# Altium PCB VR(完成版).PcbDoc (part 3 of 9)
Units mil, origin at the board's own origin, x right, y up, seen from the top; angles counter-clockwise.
Board outline 2839.68 x 2020.7 mil, 6 copper layers (TOP, GND02, SIN03, SIN04, PWR05, BOTTOM); 494 components, 404 nets, 7124 pads, 1123 vias.
Unrouted connection lines stored in the file: 10.
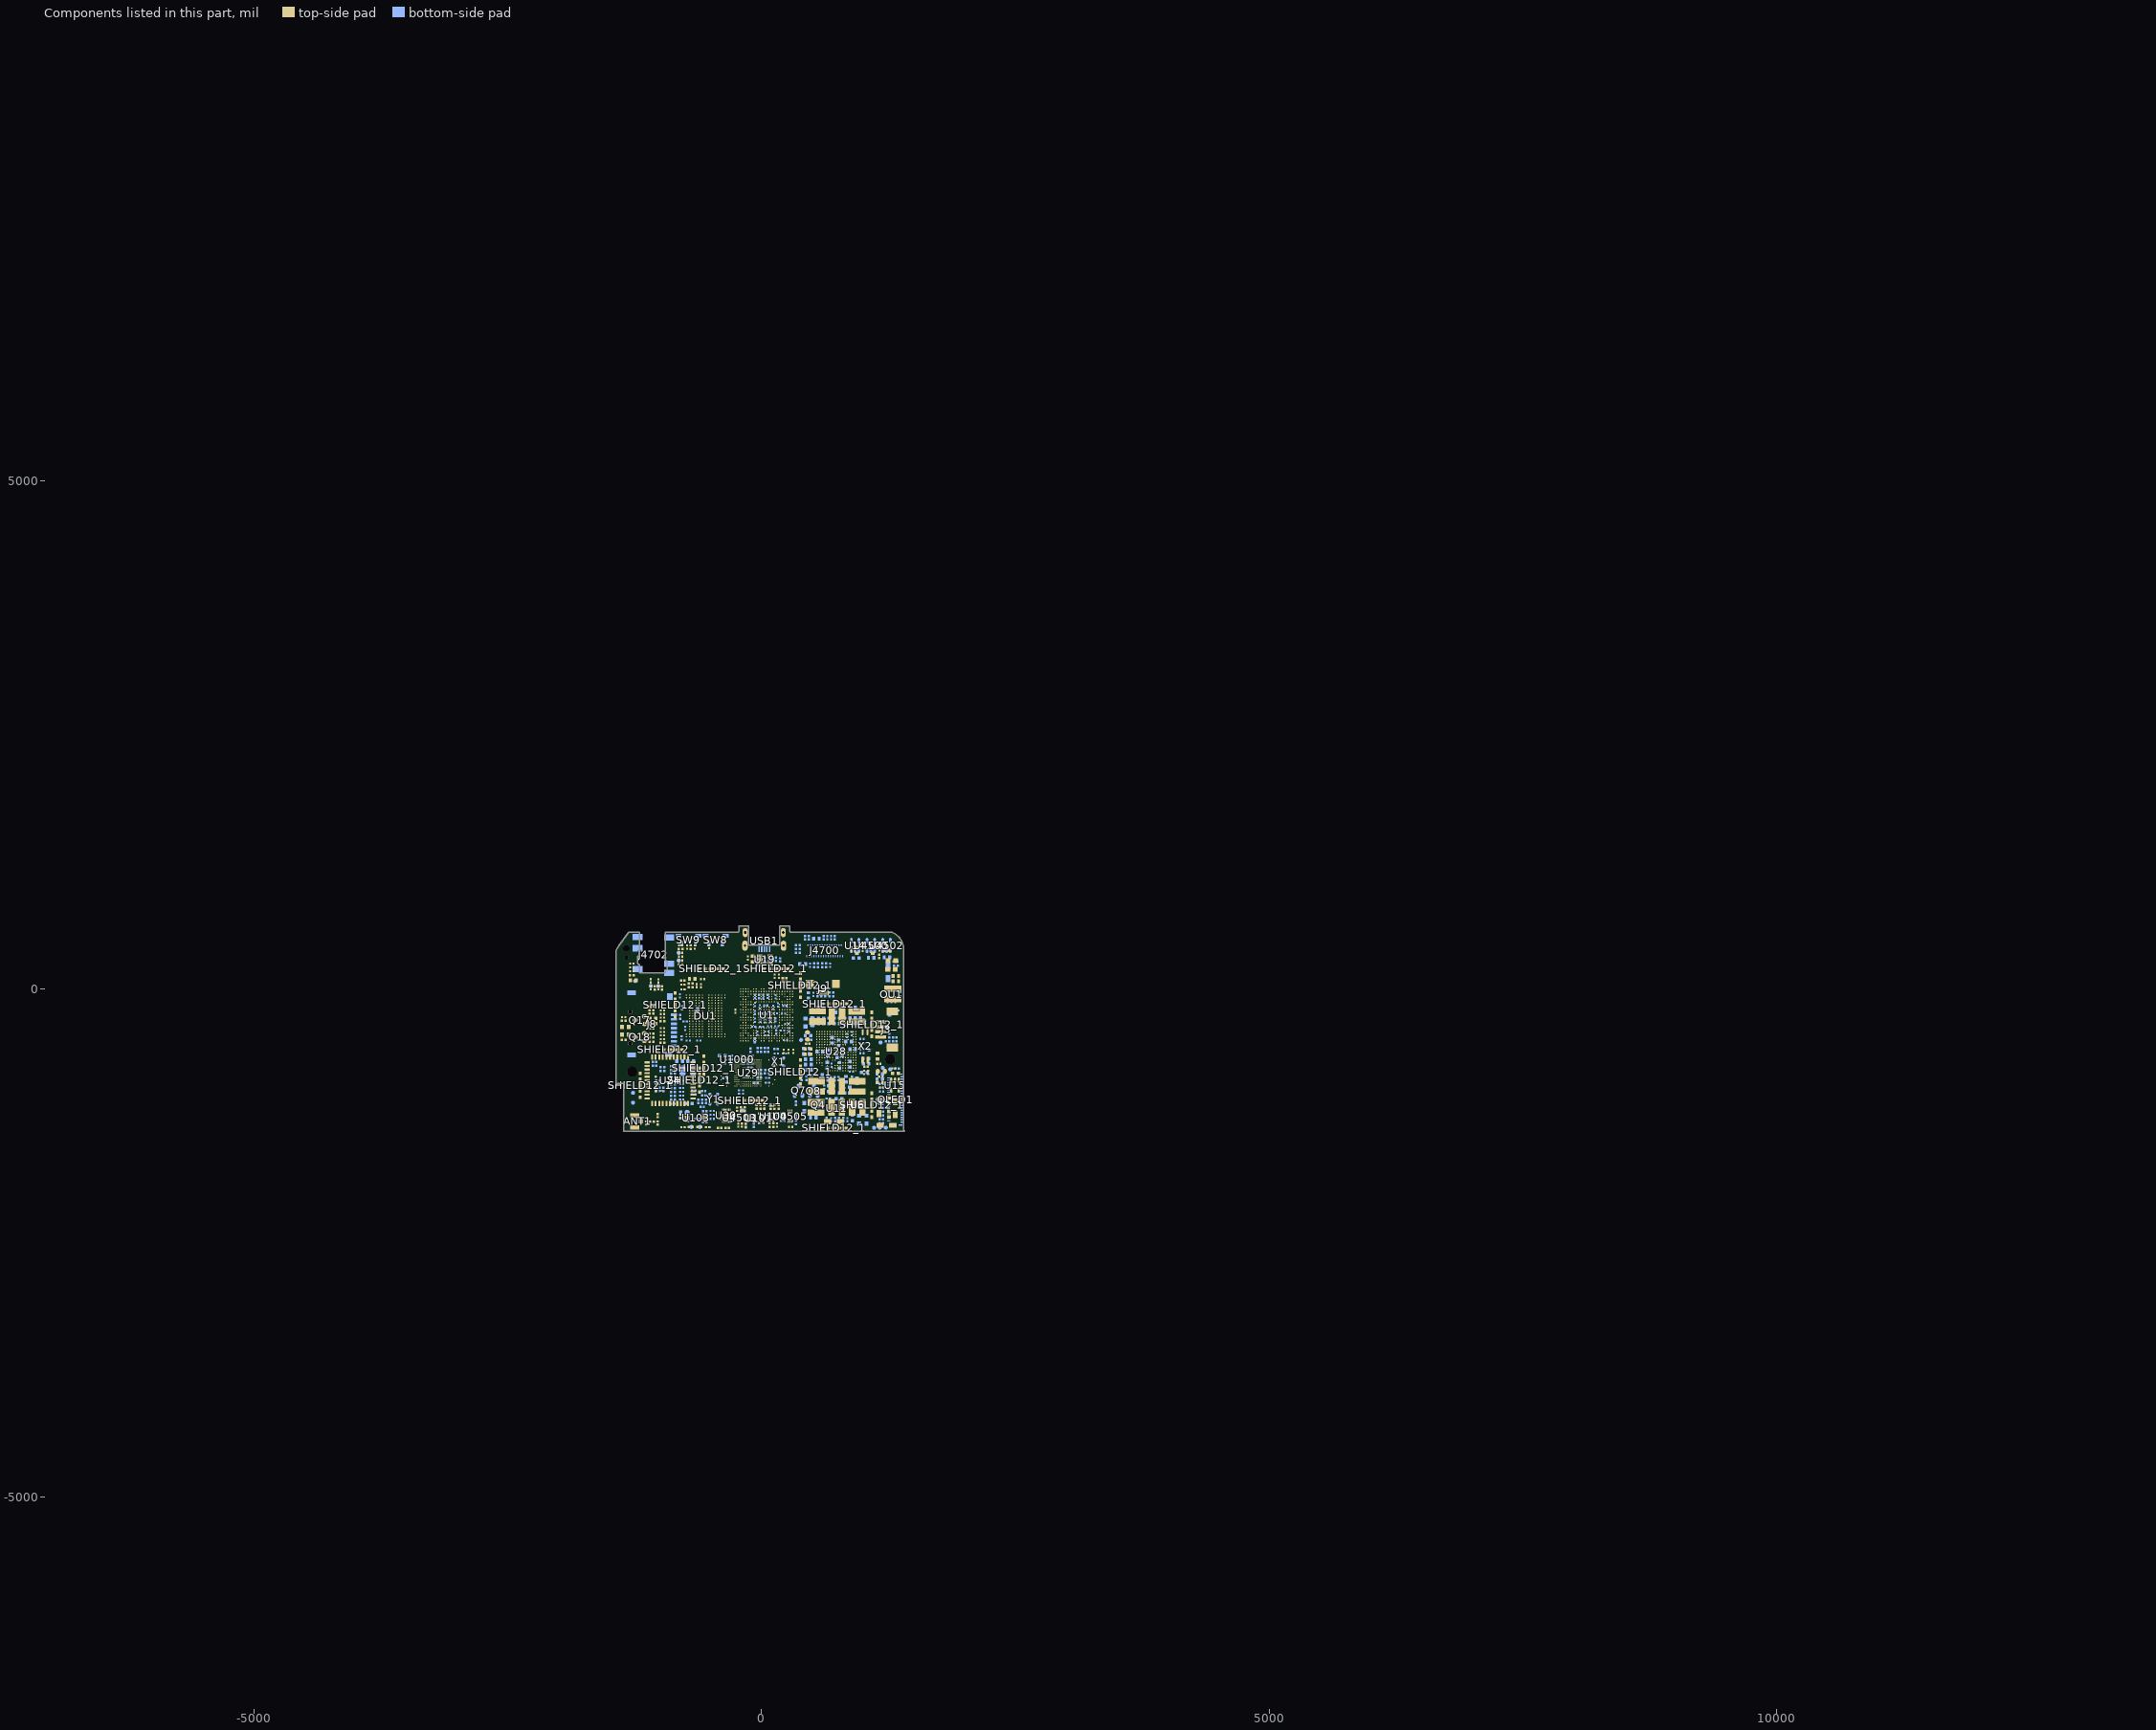
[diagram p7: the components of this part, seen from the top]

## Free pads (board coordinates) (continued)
  round 5.12 on Drill Drawing: 1(6523.34,-4195.92) 1(6523.34,-4188.83) 1(6523.34,4037.99) 1(6523.34,4091.49) 1(6523.34,5409.21) 1(6523.34,5556.46) 1(6523.34,5713.15) 1(6523.34,5773.07) 1(6523.34,5773.07) 1(6523.34,5863.15) 1(6523.34,6013.15) 1(6523.34,6163.15) 1(6523.34,6313.15) 1(6523.34,6463.15) 1(6523.34,6613.55) 1(6523.34,6663.55) 1(6523.34,6813.55) 1(6523.34,6963.55) 1(6523.34,7113.55) 1(6523.34,7413.55) 1(6523.34,7463.55) 1(6523.34,7613.55) 1(6523.34,7613.55) 1(6523.35,-412.84) 1(6523.35,-359.3) 1(6648.18,5309.56) 1(6648.18,5309.56) 1(6648.18,5314.22) 1(6648.18,5314.22) 1(6649.18,5304.89) 1(6649.18,5304.89) 1(6649.18,5318.89) 1(6649.18,5318.89) 1(6651.18,5300.81) 1(6651.18,5300.81) 1(6651.18,5322.97) 1(6651.18,5322.97) 1(6654.18,5297.31) 1(6654.18,5297.31) 1(6654.18,5326.47) 1(6654.18,5326.47) 1(6657.68,5294.97) 1(6657.68,5294.97) 1(6657.68,5328.81) 1(6657.68,5328.81) 1(6661.68,5294.39) 1(6661.68,5294.39) 1(6661.68,5329.39) 1(6661.68,5329.39) 1(6665.68,5294.97) 1(6665.68,5294.97) 1(6665.68,5328.81) 1(6665.68,5328.81) 1(6669.18,5297.31) 1(6669.18,5297.31) 1(6669.18,5326.47) 1(6669.18,5326.47) 1(6672.18,5300.81) 1(6672.18,5300.81) 1(6672.18,5322.97) 1(6672.18,5322.97) 1(6674.18,5304.89) 1(6674.18,5304.89) 1(6674.18,5318.89) 1(6674.18,5318.89) 1(6675.18,5309.56) 1(6675.18,5309.56) 1(6675.18,5314.22) 1(6675.18,5314.22) 1(6684.68,5317.72) 1(6691.68,5294.39) 1(6691.68,5329.39) 1(6698.68,5317.72) 1(6713.18,5294.39) 1(6713.18,5312.47) 1(6713.18,5329.39) 1(6715.68,5315.39) 1(6715.68,5315.39) 1(6718.18,5317.14) 1(6718.18,5317.14) 1(6722.18,5317.72) 1(6722.18,5317.72) 1(6725.18,5317.14) 1(6725.18,5317.14) 1(6728.68,5314.81) 1(6728.68,5314.81) 1(6730.18,5294.39) 1(6730.18,5311.31) 1(6730.18,5311.31) 1(6743.18,5304.31) 1(6743.18,5304.31) 1(6743.18,5307.81) 1(6743.18,5307.81) 1(6744.18,5300.81) 1(6744.18,5300.81) 1(6744.18,5310.14) 1(6744.18,5311.31) 1(6744.18,5311.31) 1(6746.18,5315.39) 1(6746.18,5315.39) 1(6746.68,5297.31) 1(6746.68,5297.31) 1(6749.18,5317.14) 1(6749.18,5317.14) 1(6749.68,5294.97) 1(6749.68,5294.97) 1(6752.68,5317.72) 1(6752.68,5317.72) 1(6753.18,5294.39) 1(6753.18,5294.39) 1(6756.18,5316.56) 1(6756.18,5316.56) 1(6756.68,5295.56) 1(6756.68,5295.56) 1(6758.68,5314.22) 1(6758.68,5314.22) 1(6760.18,5299.06) 1(6760.18,5310.14) 1(6760.18,5310.14) 1(6774.68,5294.39) 1(6774.68,5313.06) 1(6774.68,5317.72) 1(6777.18,5315.39) 1(6777.18,5315.39) 1(6779.68,5317.14) 1(6779.68,5317.14) 1(6783.18,5317.72) 1(6783.18,5317.72) 1(6785.68,5317.14) 1(6785.68,5317.14) 1(6788.68,5315.39) 1(6830.18,5294.39) 1(6830.18,5329.39) 1(6830.18,5329.39) 1(6853.18,5294.39) 1(6853.18,5294.39) 1(6853.18,5329.39) 1(6856.9,-4023.04) 1(6856.9,-4023.04) 1(6856.9,-4023.04) 1(6856.9,-4023.04) 1(6856.9,-4023.04) 1(6856.9,-4023.04) 1(6856.9,-3913.2) 1(6856.9,-3913.2) 1(6856.9,-3803.36) 1(6856.9,-3803.36) 1(6856.9,-3693.52) 1(6856.9,-3693.52) 1(6856.9,-3583.67) 1(6856.9,-3583.67) 1(6856.9,-3473.83) 1(6856.9,-3473.83) 1(6856.9,-3363.99) 1(6856.9,-3363.99) 1(6856.9,-3254.14) 1(6856.9,-3254.14) 1(6856.9,-3144.3) 1(6856.9,-3144.3) 1(6856.9,-3034.46) 1(6856.9,-3034.46) 1(6856.9,-2924.62) 1(6856.9,-2924.62) 1(6856.9,-2814.77) 1(6856.9,-2814.77) 1(6856.9,-2704.93) 1(6856.9,-2704.93) 1(6856.9,-2704.93) 1(6856.9,-2704.93) 1(6856.9,-2704.93) 1(6856.9,-2704.93) 1(6856.9,-2485.25) 1(6856.9,-2485.25) 1(6856.9,-2485.25) 1(6856.9,-2375.4) 1(6856.9,-2265.56) 1(6856.9,-2155.72) 1(6856.9,-2045.88) 1(6856.9,-1936.03) 1(6856.9,-1826.19) 1(6856.9,-1716.35) 1(6856.9,-1606.51) 1(6856.9,-1496.66) 1(6856.9,-1386.82) 1(6856.9,-1276.98) 1(6856.9,-1167.13) 1(6856.9,-1057.29) 1(6856.9,-947.45) 1(6856.9,-837.61) 1(6856.9,-727.76) 1(6856.9,-617.92) 1(6856.9,-617.92) 1(6856.9,-617.92) 1(6862.68,5306.06) 1(6862.68,5306.06) 1(6863.68,5301.39) 1(6863.68,5301.39) 1(6863.68,5310.72) 1(6863.68,5310.72) 1(6865.68,5297.31) 1(6865.68,5297.31) 1(6865.68,5314.81) 1(6865.68,5314.81) 1(6868.68,5294.97) 1(6868.68,5294.97) 1(6868.68,5317.14) 1(6868.68,5317.14) 1(6871.68,5294.39) 1(6871.68,5294.39) 1(6871.68,5317.72) 1(6871.68,5317.72) 1(6874.68,5294.97) 1(6874.68,5294.97) 1(6874.68,5317.14) 1(6874.68,5317.14) 1(6877.68,5297.31) 1(6877.68,5297.31) 1(6877.68,5314.81) 1(6877.68,5314.81) 1(6879.68,5301.39) 1(6879.68,5301.39) 1(6879.68,5310.72) 1(6879.68,5310.72) 1(6880.18,5306.06) 1(6880.18,5306.06) 1(6894.68,5317.72) 1(6901.68,5294.39) 1(6901.68,5329.39) 1(6908.68,5317.72) 1(6923.18,5304.31) 1(6923.18,5304.31) 1(6923.18,5307.81) 1(6923.18,5307.81) 1(6924.18,5300.81) 1(6924.18,5300.81) 1(6924.18,5310.14) 1(6924.18,5311.31) 1(6924.18,5311.31) 1(6926.18,5315.39) 1(6926.18,5315.39) 1(6926.68,5297.31) 1(6926.68,5297.31) 1(6929.18,5317.14) 1(6929.18,5317.14) 1(6929.68,5294.97) 1(6929.68,5294.97) 1(6932.68,5317.72) 1(6932.68,5317.72) 1(6933.18,5294.39) 1(6933.18,5294.39) 1(6936.18,5316.56) 1(6936.18,5316.56) 1(6936.68,5295.56) 1(6936.68,5295.56) 1(6938.68,5314.22) 1(6938.68,5314.22) 1(6940.18,5299.06) 1(6940.18,5310.14) 1(6940.18,5310.14) 1(6954.18,5298.47) 1(6955.68,5312.47) 1(6955.68,5312.47) 1(6956.68,5296.14) 1(6956.68,5296.14) 1(6956.68,5315.39) 1(6956.68,5315.39) 1(6957.68,5308.39) 1(6957.68,5308.39) 1(6958.68,5317.14) 1(6958.68,5317.14) 1(6960.18,5294.39) 1(6960.18,5294.39) 1(6961.68,5317.72) 1(6961.68,5317.72) 1(6963.18,5294.39) 1(6963.18,5294.39) 1(6964.68,5317.14) 1(6964.68,5317.14) 1(6966.18,5295.56) 1(6966.18,5295.56) 1(6966.68,5304.89) 1(6966.68,5304.89) 1(6967.68,5315.39) 1(6968.18,5297.31) 1(6968.18,5297.31) 1(6968.68,5303.14) 1(6968.68,5303.14) 1(6969.18,5299.64) 1(6969.18,5299.64) 1(6990.68,5293.81) 1(6990.68,5293.81) 1(6990.68,5294.97) 1(6990.68,5294.97) 1(6990.68,5309.56) 1(6990.68,5309.56) 1(6990.68,5310.72) 1(6990.68,5310.72) 1(6991.68,5293.22) 1(6991.68,5293.22) 1(6991.68,5295.56) 1(6991.68,5295.56) 1(6991.68,5308.97) 1(6991.68,5308.97) 1(6991.68,5311.31) 1(6991.68,5311.31) 1(6992.68,5293.81) 1(6992.68,5293.81) 1(6992.68,5294.97) 1(6992.68,5294.97) 1(6992.68,5309.56) 1(6992.68,5309.56) 1(6992.68,5310.72) 1(6992.68,5310.72) 1(7306.9,-2485.25) 1(7306.9,-2485.25) 1(7306.9,-2485.25) 1(7306.9,-2485.25) 1(7306.9,-767.92) 1(7306.9,-617.92) 1(7306.9,-617.92) 1(7306.9,-617.92) 1(7306.9,-617.92) 1(7306.9,-617.92) 1(7356.9,-4023.04) 1(7356.9,-4023.04) 1(7356.9,-2704.93) 1(7356.9,-2704.93) 1(7373.35,5713.15) 1(7373.35,5863.15) 1(7373.35,5863.15) 1(7373.35,6013.15) 1(7373.35,6013.15) 1(7373.35,6163.15) 1(7373.35,6163.15) 1(7373.35,6313.15) 1(7373.35,6313.15) 1(7373.35,6611.18) 1(7373.35,6663.55) 1(7373.35,6813.55) 1(7373.35,6813.55) 1(7373.35,6963.55) 1(7373.35,6963.55) 1(7373.35,7113.55) 1(7373.35,7113.55) 1(7373.35,7263.55) 1(7373.35,7263.55) 1(7373.35,7263.55) 1(7373.35,7413.55) 1(7373.35,7463.85) 1(7373.35,7613.55) 1(7418.74,5736.21) 1(7418.74,5736.21) 1(7418.74,5836.21) 1(7418.74,5836.21) 1(7423.35,6038.35) 1(7423.35,6038.35) 1(7423.35,6138.35) 1(7423.35,6138.35) 1(7423.35,6188.35) 1(7423.35,6188.35) 1(7423.35,6288.35) 1(7423.35,6288.35) 1(7423.35,6338.35) 1(7423.35,6338.35) 1(7423.35,6338.35) 1(7423.35,6338.35) 1(7423.35,6438.35) 1(7423.35,6438.35) 1(7423.35,6438.35) 1(7423.35,6438.35) 1(7423.35,6688.35) 1(7423.35,6688.35) 1(7423.35,6688.35) 1(7423.35,6688.35) 1(7423.35,6788.35) 1(7423.35,6788.35) 1(7423.35,6788.35) 1(7423.35,6788.35) 1(7423.35,6838.35) 1(7423.35,6838.35) 1(7423.35,6838.35) 1(7423.35,6838.35) 1(7423.35,6938.35) 1(7423.35,6938.35) 1(7423.35,6938.35) 1(7423.35,6938.35) 1(7423.35,6988.35) 1(7423.35,6988.35) 1(7423.35,7088.35) 1(7423.35,7088.35) 1(7423.35,7138.35) 1(7423.35,7138.35) 1(7423.35,7238.35) 1(7423.35,7238.35) 1(7423.55,6193.35) 1(7423.55,6193.35) 1(7423.55,6193.35) 1(7423.55,6193.35) 1(7423.55,6293.35) 1(7423.55,6293.35) 1(7423.55,6293.35) 1(7423.55,6293.35) 1(7428.47,6347.59) 1(7428.47,6351.71) 1(7428.47,6355.83) 1(7428.47,6359.95) 1(7428.47,6364.07) 1(7428.47,6368.19) 1(7428.47,6372.31) 1(7428.47,6376.43) 1(7428.47,6380.55) 1(7428.47,6384.67) 1(7428.47,6388.79) 1(7428.47,6392.91) 1(7428.47,6397.03) 1(7428.47,6401.15) 1(7428.47,6405.27) 1(7428.47,6409.39) 1(7428.47,6413.51) 1(7428.47,6417.63) 1(7428.47,6421.75) 1(7428.47,6425.87) 1(7428.47,6429.99) 1(7428.47,6697.59) 1(7428.47,6701.71) 1(7428.47,6705.83) 1(7428.47,6709.95) 1(7428.47,6714.07) 1(7428.47,6718.19) 1(7428.47,6722.31) 1(7428.47,6726.43) 1(7428.47,6730.55) 1(7428.47,6734.67) 1(7428.47,6738.79) 1(7428.47,6742.91) 1(7428.47,6747.03) 1(7428.47,6751.15) 1(7428.47,6755.27) 1(7428.47,6759.39) 1(7428.47,6763.51) 1(7428.47,6767.63) 1(7428.47,6771.75) 1(7428.47,6775.87) 1(7428.47,6779.99) 1(7428.47,6847.59) 1(7428.47,6851.71) 1(7428.47,6855.83) 1(7428.47,6859.95) 1(7428.47,6864.07) 1(7428.47,6868.19) 1(7428.47,6872.31) 1(7428.47,6876.43) 1(7428.47,6880.55) 1(7428.47,6884.67) 1(7428.47,6888.79) 1(7428.47,6892.91) 1(7428.47,6897.03) 1(7428.47,6901.15) 1(7428.47,6905.27) 1(7428.47,6909.39) 1(7428.47,6913.51) 1(7428.47,6917.63) 1(7428.47,6921.75) 1(7428.47,6925.87) 1(7428.47,6929.99) 1(7428.67,6202.59) 1(7428.67,6206.71) 1(7428.67,6210.83) 1(7428.67,6214.95) 1(7428.67,6219.07) 1(7428.67,6223.19) 1(7428.67,6227.31) 1(7428.67,6231.43) 1(7428.67,6235.55) 1(7428.67,6239.67) 1(7428.67,6243.79) 1(7428.67,6247.91) 1(7428.67,6252.03) 1(7428.67,6256.15) 1(7428.67,6260.27) 1(7428.67,6264.39) 1(7428.67,6268.51) 1(7428.67,6272.63) 1(7428.67,6276.75) 1(7428.67,6280.87) 1(7428.67,6284.99) 1(7429.1,7288.74) 1(7429.1,7288.74) 1(7429.1,7388.74) 1(7429.1,7388.74) 1(7518.23,6347.59) 1(7518.23,6351.71) 1(7518.23,6355.83) 1(7518.23,6359.95) 1(7518.23,6364.07) 1(7518.23,6368.19) 1(7518.23,6372.31) 1(7518.23,6376.43) 1(7518.23,6380.55) 1(7518.23,6384.67) 1(7518.23,6388.79) 1(7518.23,6392.91) 1(7518.23,6397.03) 1(7518.23,6401.15) 1(7518.23,6405.27) 1(7518.23,6409.39) 1(7518.23,6413.51) 1(7518.23,6417.63) 1(7518.23,6421.75) 1(7518.23,6425.87) 1(7518.23,6429.99) 1(7518.23,6697.59) 1(7518.23,6701.71) 1(7518.23,6705.83) 1(7518.23,6709.95) 1(7518.23,6714.07) 1(7518.23,6718.19) 1(7518.23,6722.31) 1(7518.23,6726.43) 1(7518.23,6730.55) 1(7518.23,6734.67) 1(7518.23,6738.79) 1(7518.23,6742.91) 1(7518.23,6747.03) 1(7518.23,6751.15) 1(7518.23,6755.27) 1(7518.23,6759.39) 1(7518.23,6763.51) 1(7518.23,6767.63) 1(7518.23,6771.75) 1(7518.23,6775.87) 1(7518.23,6779.99) 1(7518.23,6847.59) 1(7518.23,6851.71) 1(7518.23,6855.83) 1(7518.23,6859.95) 1(7518.23,6864.07) 1(7518.23,6868.19) 1(7518.23,6872.31) 1(7518.23,6876.43) 1(7518.23,6880.55) 1(7518.23,6884.67) 1(7518.23,6888.79) 1(7518.23,6892.91) 1(7518.23,6897.03) 1(7518.23,6901.15) 1(7518.23,6905.27) 1(7518.23,6909.39) 1(7518.23,6913.51) 1(7518.23,6917.63) 1(7518.23,6921.75) 1(7518.23,6925.87) 1(7518.23,6929.99) 1(7518.43,6202.59) 1(7518.43,6206.71) 1(7518.43,6210.83) 1(7518.43,6214.95) 1(7518.43,6219.07) 1(7518.43,6223.19) 1(7518.43,6227.31) 1(7518.43,6231.43) 1(7518.43,6235.55) 1(7518.43,6239.67) 1(7518.43,6243.79) 1(7518.43,6247.91) 1(7518.43,6252.03) 1(7518.43,6256.15) 1(7518.43,6260.27) 1(7518.43,6264.39) 1(7518.43,6268.51) 1(7518.43,6272.63) 1(7518.43,6276.75) 1(7518.43,6280.87) 1(7518.43,6284.99) 1(7518.74,5736.21) 1(7518.74,5736.21) 1(7518.74,5836.21) 1(7518.74,5836.21) 1(7523.35,6038.35) 1(7523.35,6038.35) 1(7523.35,6138.35) 1(7523.35,6138.35) 1(7523.35,6188.35) 1(7523.35,6188.35) 1(7523.35,6288.35) 1(7523.35,6288.35) 1(7523.35,6338.35) 1(7523.35,6338.35) 1(7523.35,6338.35) 1(7523.35,6338.35) 1(7523.35,6438.35) 1(7523.35,6438.35) 1(7523.35,6438.35) 1(7523.35,6438.35) 1(7523.35,6688.35) 1(7523.35,6688.35) 1(7523.35,6688.35) 1(7523.35,6688.35) 1(7523.35,6788.35) 1(7523.35,6788.35) 1(7523.35,6788.35) 1(7523.35,6788.35) 1(7523.35,6838.35) 1(7523.35,6838.35) 1(7523.35,6838.35) 1(7523.35,6838.35) 1(7523.35,6938.35) 1(7523.35,6938.35) 1(7523.35,6938.35) 1(7523.35,6938.35) 1(7523.35,6988.35) 1(7523.35,6988.35) 1(7523.35,7088.35) 1(7523.35,7088.35) 1(7523.35,7138.35) 1(7523.35,7138.35) 1(7523.35,7238.35) 1(7523.35,7238.35) 1(7523.55,6193.35) 1(7523.55,6193.35) 1(7523.55,6193.35) 1(7523.55,6193.35) 1(7523.55,6293.35) 1(7523.55,6293.35) 1(7523.55,6293.35) 1(7523.55,6293.35) 1(7529.1,7288.74) 1(7529.1,7288.74) 1(7529.1,7388.74) 1(7529.1,7388.74) 1(7956.9,-4023.04) 1(7956.9,-4023.04) 1(7956.9,-2704.93) 1(7956.9,-2704.93) 1(7956.9,-2485.25) 1(7956.9,-2485.25) 1(7956.9,-2485.25) 1(7956.9,-2485.25) 1(7956.9,-767.92) 1(7956.9,-617.92) 1(7956.9,-617.92) 1(7956.9,-617.92) 1(7956.9,-617.92) 1(7956.9,-617.92) 1(7998.55,7463.55) 1(7998.55,7613.55) 1(8098.12,6988.35) 1(8098.12,6988.35) 1(8098.12,7088.35) 1(8098.12,7088.35) 1(8098.12,7138.35) 1(8098.12,7138.35) 1(8098.12,7238.35) 1(8098.12,7238.35) 1(8098.12,7288.35) 1(8098.12,7288.35) 1(8098.12,7388.35) 1(8098.12,7388.35) 1(8098.55,6038.35) 1(8098.55,6038.35) 1(8098.55,6038.35) 1(8098.55,6038.35) 1(8098.55,6138.35) 1(8098.55,6138.35) 1(8098.55,6138.35) 1(8098.55,6138.35) 1(8098.55,6188.35) 1(8098.55,6188.35) 1(8098.55,6288.35) 1(8098.55,6288.35) 1(8098.55,6338.35) 1(8098.55,6338.35) 1(8098.55,6438.35) 1(8098.55,6438.35) 1(8098.55,6688.35) 1(8098.55,6688.35) 1(8098.55,6788.35) 1(8098.55,6788.35) 1(8098.55,6838.35) 1(8098.55,6838.35) 1(8098.55,6938.35) 1(8098.55,6938.35) 1(8103.67,6047.59) 1(8103.67,6051.71) 1(8103.67,6055.83) 1(8103.67,6059.95) 1(8103.67,6064.07) 1(8103.67,6068.19) 1(8103.67,6072.31) 1(8103.67,6076.43) 1(8103.67,6080.55) 1(8103.67,6084.67) 1(8103.67,6088.79) 1(8103.67,6092.91) 1(8103.67,6097.03) 1(8103.67,6101.15) 1(8103.67,6105.27) 1(8103.67,6109.39) 1(8103.67,6113.51) 1(8103.67,6117.63) 1(8103.67,6121.75) 1(8103.67,6125.87) 1(8103.67,6129.99) 1(8193.43,6047.59) 1(8193.43,6051.71) 1(8193.43,6055.83) 1(8193.43,6059.95) 1(8193.43,6064.07) 1(8193.43,6068.19) 1(8193.43,6072.31) 1(8193.43,6076.43) 1(8193.43,6080.55) 1(8193.43,6084.67) 1(8193.43,6088.79) 1(8193.43,6092.91) 1(8193.43,6097.03) 1(8193.43,6101.15) 1(8193.43,6105.27) 1(8193.43,6109.39) 1(8193.43,6113.51) 1(8193.43,6117.63) 1(8193.43,6121.75) 1(8193.43,6125.87) 1(8193.43,6129.99) 1(8198.12,6988.35) 1(8198.12,6988.35) 1(8198.12,7088.35) 1(8198.12,7088.35) 1(8198.12,7138.35) 1(8198.12,7138.35) 1(8198.12,7238.35) 1(8198.12,7238.35) 1(8198.12,7288.35) 1(8198.12,7288.35) 1(8198.12,7388.35) 1(8198.12,7388.35) 1(8198.55,6038.35) 1(8198.55,6038.35) 1(8198.55,6038.35) 1(8198.55,6038.35) 1(8198.55,6138.35) 1(8198.55,6138.35) 1(8198.55,6138.35) 1(8198.55,6138.35) 1(8198.55,6188.35) 1(8198.55,6188.35) 1(8198.55,6288.35) 1(8198.55,6288.35) 1(8198.55,6338.35) 1(8198.55,6338.35) 1(8198.55,6438.35) 1(8198.55,6438.35) 1(8198.55,6688.35) 1(8198.55,6688.35) 1(8198.55,6788.35) 1(8198.55,6788.35) 1(8198.55,6838.35) 1(8198.55,6838.35) 1(8198.55,6938.35) 1(8198.55,6938.35) 1(8656.9,-4023.04) 1(8656.9,-4023.04) 1(8656.9,-4023.04) 1(8656.9,-4023.04) 1(8656.9,-2704.93) 1(8656.9,-2704.93) 1(8656.9,-2704.93) 1(8656.9,-2704.93) 1(8656.9,-2485.25) 1(8656.9,-2485.25) 1(8656.9,-767.92) 1(8656.9,-617.92) 1(8656.9,-617.92) 1(8656.9,-617.92) 1(8673.35,6462.36) 1(8673.35,6613.94) 1(8723.35,7288.35) 1(8723.35,7288.35) 1(8723.35,7288.35) 1(8723.35,7288.35) 1(8723.35,7388.35) 1(8723.35,7388.35) 1(8723.35,7388.35) 1(8723.35,7388.35) 1(8723.35,6688.35) 1(8723.35,6688.35) 1(8723.35,6788.35) 1(8723.35,6788.35) 1(8723.35,6838.35) 1(8723.35,6838.35) 1(8723.35,6938.35) 1(8723.35,6938.35) 1(8724.1,6988.74) 1(8724.1,6988.74) 1(8724.1,7088.74) 1(8724.1,7088.74) 1(8724.1,7138.74) 1(8724.1,7138.74) 1(8724.1,7238.74) 1(8724.1,7238.74) 1(8724.1,7288.74) 1(8724.1,7288.74) 1(8724.1,7388.74) 1(8724.1,7388.74) 1(8728.47,7297.59) 1(8728.47,7301.71) 1(8728.47,7305.83) 1(8728.47,7309.95) 1(8728.47,7314.07) 1(8728.47,7318.19) 1(8728.47,7322.31) 1(8728.47,7326.43) 1(8728.47,7330.55) 1(8728.47,7334.67) 1(8728.47,7338.79) 1(8728.47,7342.91) 1(8728.47,7347.03) 1(8728.47,7351.15) 1(8728.47,7355.27) 1(8728.47,7359.39) 1(8728.47,7363.51) 1(8728.47,7367.63) 1(8728.47,7371.75) 1(8728.47,7375.87) 1(8728.47,7379.99) 1(8818.23,7297.59) 1(8818.23,7301.71) 1(8818.23,7305.83) 1(8818.23,7309.95) 1(8818.23,7314.07) 1(8818.23,7318.19) 1(8818.23,7322.31) 1(8818.23,7326.43) 1(8818.23,7330.55) 1(8818.23,7334.67) 1(8818.23,7338.79) 1(8818.23,7342.91) 1(8818.23,7347.03) 1(8818.23,7351.15) 1(8818.23,7355.27) 1(8818.23,7359.39) 1(8818.23,7363.51) 1(8818.23,7367.63) 1(8818.23,7371.75) 1(8818.23,7375.87) 1(8818.23,7379.99) 1(8823.35,7288.35) 1(8823.35,7288.35) 1(8823.35,7288.35) 1(8823.35,7288.35) 1(8823.35,7388.35) 1(8823.35,7388.35) 1(8823.35,7388.35) 1(8823.35,7388.35) 1(8823.35,6688.35) 1(8823.35,6688.35) 1(8823.35,6788.35) 1(8823.35,6788.35) 1(8823.35,6838.35) 1(8823.35,6838.35) 1(8823.35,6938.35) 1(8823.35,6938.35) 1(8824.1,6988.74) 1(8824.1,6988.74) 1(8824.1,7088.74) 1(8824.1,7088.74) 1(8824.1,7138.74) 1(8824.1,7138.74) 1(8824.1,7238.74) 1(8824.1,7238.74) 1(8824.1,7288.74) 1(8824.1,7288.74) 1(8824.1,7388.74) 1(8824.1,7388.74) 1(8860.66,7463.55) 1(8860.66,7613.25) 1(9098.55,6338.35) 1(9098.55,6338.35) 1(9098.55,6438.35) 1(9098.55,6438.35) 1(9108.55,6188.35) 1(9108.55,6188.35) 1(9108.55,6288.35) 1(9108.55,6288.35) 1(9198.55,6338.35) 1(9198.55,6338.35) 1(9198.55,6438.35) 1(9198.55,6438.35) 1(9208.55,6188.35) 1(9208.55,6188.35) 1(9208.55,6288.35) 1(9208.55,6288.35) 1(9223.35,6463.15) 1(9223.35,6613.55) 1(9256.9,-4023.04) 1(9256.9,-4023.04) 1(9256.9,-4023.04) 1(9256.9,-4023.04) 1(9256.9,-2704.93) 1(9256.9,-2704.93) 1(9256.9,-2704.93) 1(9256.9,-2704.93) 1(9256.9,-2485.25) 1(9256.9,-2485.25) 1(9256.9,-767.92) 1(9256.9,-617.92) 1(9256.9,-617.92) 1(9256.9,-617.92) 1(9373.35,7463.55) 1(9373.35,7613.55) 1(9497.72,6688.35) 1(9497.72,6688.35) 1(9497.72,6788.35) 1(9497.72,6788.35) 1(9497.72,6838.35) 1(9497.72,6838.35) 1(9497.72,6938.35) 1(9497.72,6938.35) 1(9497.72,6988.35) 1(9497.72,6988.35) 1(9497.72,7088.35) 1(9497.72,7088.35) 1(9498.12,7138.35) 1(9498.12,7138.35) 1(9498.12,7238.35) 1(9498.12,7238.35) 1(9498.12,7288.35) 1(9498.12,7288.35) 1(9498.12,7388.35) 1(9498.12,7388.35) 1(9597.72,6688.35) 1(9597.72,6688.35) 1(9597.72,6788.35) 1(9597.72,6788.35) 1(9597.72,6838.35) 1(9597.72,6838.35) 1(9597.72,6938.35) 1(9597.72,6938.35) 1(9597.72,6988.35) 1(9597.72,6988.35) 1(9597.72,7088.35) 1(9597.72,7088.35) 1(9598.12,7138.35) 1(9598.12,7138.35) 1(9598.12,7238.35) 1(9598.12,7238.35) 1(9598.12,7288.35) 1(9598.12,7288.35) 1(9598.12,7388.35) 1(9598.12,7388.35) 1(9824.85,7463.55) 1(9824.85,7613.55) 1(10006.91,-4023.04) 1(10006.91,-4023.04) 1(10006.91,-4023.04) 1(10006.91,-4023.04) 1(10006.91,-2704.93) 1(10006.91,-2704.93) 1(10006.91,-2704.93) 1(10006.91,-2704.93) 1(10006.91,-2485.25) 1(10006.91,-2485.25) 1(10006.91,-2485.25) 1(10006.91,-2485.25) 1(10006.91,-767.92) 1(10006.91,-617.92) 1(10006.91,-617.92) 1(10006.91,-617.92) 1(10006.91,-617.92) 1(10006.91,-617.92) 1(10073.35,5738.35) 1(10073.35,5738.35) 1(10073.35,5738.35) 1(10073.35,5738.35) 1(10073.35,5738.35) 1(10073.35,5738.35) 1(10073.35,5838.35) 1(10073.35,5838.35) 1(10073.35,5838.35) 1(10073.35,5838.35) 1(10073.35,5838.35) 1(10073.35,5838.35) 1(10073.35,6188.35) 1(10073.35,6188.35) 1(10073.35,6288.35) 1(10073.35,6288.35) 1(10073.35,6338.35) 1(10073.35,6338.35) 1(10073.35,6438.35) 1(10073.35,6438.35) 1(10078.47,5747.59) 1(10078.47,5751.71) 1(10078.47,5755.83) 1(10078.47,5759.95) 1(10078.47,5764.07) 1(10078.47,5768.19) 1(10078.47,5772.31) 1(10078.47,5776.43) 1(10078.47,5780.55) 1(10078.47,5784.67) 1(10078.47,5788.79) 1(10078.47,5792.91) 1(10078.47,5797.03) 1(10078.47,5801.15) 1(10078.47,5805.27) 1(10078.47,5809.39) 1(10078.47,5813.51) 1(10078.47,5817.63) 1(10078.47,5821.75) 1(10078.47,5825.87) 1(10078.47,5829.99) 1(10168.23,5747.59) 1(10168.23,5751.71) 1(10168.23,5755.83) 1(10168.23,5759.95) 1(10168.23,5764.07) 1(10168.23,5768.19) 1(10168.23,5772.31) 1(10168.23,5776.43) 1(10168.23,5780.55) 1(10168.23,5784.67) 1(10168.23,5788.79) 1(10168.23,5792.91) 1(10168.23,5797.03) 1(10168.23,5801.15) 1(10168.23,5805.27) 1(10168.23,5809.39) 1(10168.23,5813.51) 1(10168.23,5817.63) 1(10168.23,5821.75) 1(10168.23,5825.87) 1(10168.23,5829.99) 1(10173.35,5738.35) 1(10173.35,5738.35) 1(10173.35,5738.35) 1(10173.35,5738.35) 1(10173.35,5838.35) 1(10173.35,5838.35) 1(10173.35,5838.35) 1(10173.35,5838.35) 1(10173.35,5738.35) 1(10173.35,5738.35) 1(10173.35,5838.35) 1(10173.35,5838.35) 1(10173.35,6188.35) 1(10173.35,6188.35) 1(10173.35,6288.35) 1(10173.35,6288.35) 1(10173.35,6338.35) 1(10173.35,6338.35) 1(10173.35,6438.35) 1(10173.35,6438.35) 1(10185.16,6985.2) 1(10185.16,6985.2) 1(10185.16,7085.2) 1(10185.16,7085.2) 1(10185.16,7285.2) 1(10185.16,7285.2) 1(10185.16,7385.2) 1(10185.16,7385.2) 1(10285.16,6985.2) 1(10285.16,6985.2) 1(10285.16,7085.2) 1(10285.16,7085.2) 1(10285.16,7285.2) 1(10285.16,7285.2) 1(10285.16,7385.2) 1(10285.16,7385.2) 1(10456.91,-4023.04) 1(10456.91,-3913.2) 1(10456.91,-3803.36) 1(10456.91,-3693.52) 1(10456.91,-3583.67) 1(10456.91,-3473.83) 1(10456.91,-3363.99) 1(10456.91,-3254.14) 1(10456.91,-3144.3) 1(10456.91,-3034.46) 1(10456.91,-2924.62) 1(10456.91,-2814.77) 1(10456.91,-2704.93) 1(10456.91,-2704.93) 1(10481.71,-4023.04) 1(10481.71,-4023.04) 1(10481.71,-4023.04) 1(10481.71,-4023.04) 1(10481.71,-4023.04) 1(10481.71,-3913.2) 1(10481.71,-3803.36) 1(10481.71,-3693.52) 1(10481.71,-3583.67) 1(10481.71,-3473.83) 1(10481.71,-3363.99) 1(10481.71,-3254.14) 1(10481.71,-3144.3) 1(10481.71,-3034.46) 1(10481.71,-2924.62) 1(10481.71,-2814.77) 1(10481.71,-2704.93) 1(10481.71,-2704.93) 1(10481.71,-2704.93) 1(10481.71,-2704.93) 1(10481.71,-2485.25) 1(10481.71,-2485.25) 1(10481.71,-2485.25) 1(10481.71,-2375.4) 1(10481.71,-2265.56) 1(10481.71,-2155.72) 1(10481.71,-2045.88) 1(10481.71,-1936.03) 1(10481.71,-1826.19) 1(10481.71,-1716.35) 1(10481.71,-1606.51) 1(10481.71,-1496.66) 1(10481.71,-1386.82) 1(10481.71,-1276.98) 1(10481.71,-1167.13) 1(10481.71,-1057.29) 1(10481.71,-947.45) 1(10481.71,-837.61) 1(10481.71,-727.76) 1(10481.71,-617.92) 1(10481.71,-617.92) 1(10481.71,-617.92) 1(10773.35,-4188.83) 1(10773.35,-4188.83) 1(10773.35,4037.99) 1(10773.35,4091.49) 1(10773.35,5409.21) 1(10773.35,5556.46) 1(10773.35,5710.4) 1(10773.35,5713.15) 1(10773.35,5713.15) 1(10773.35,5863.15) 1(10773.35,6013.15) 1(10773.35,6163.15) 1(10773.35,6313.15) 1(10773.35,6463.15) 1(10773.35,6613.55) 1(10773.35,6663.55) 1(10773.35,6813.55) 1(10773.35,6963.55) 1(10773.35,7113.55) 1(10773.35,7263.55) 1(10773.35,7413.55) 1(10773.35,7463.55) 1(10773.35,7613.55) 1(10773.35,7613.55) 1(10773.35,-412.84) 1(10773.35,-359.3)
